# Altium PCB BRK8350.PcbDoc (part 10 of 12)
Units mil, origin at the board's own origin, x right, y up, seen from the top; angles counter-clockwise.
Board outline 9448.82 x 5905.51 mil, 8 copper layers (L1-TOP, L2-GND, L3-SIG, L4-GND, L5-PWR, L6-PWR, L7-GND, L8-BOT), stack 57.69 mil thick; 288 components, 543 nets, 1891 pads, 2032 vias.
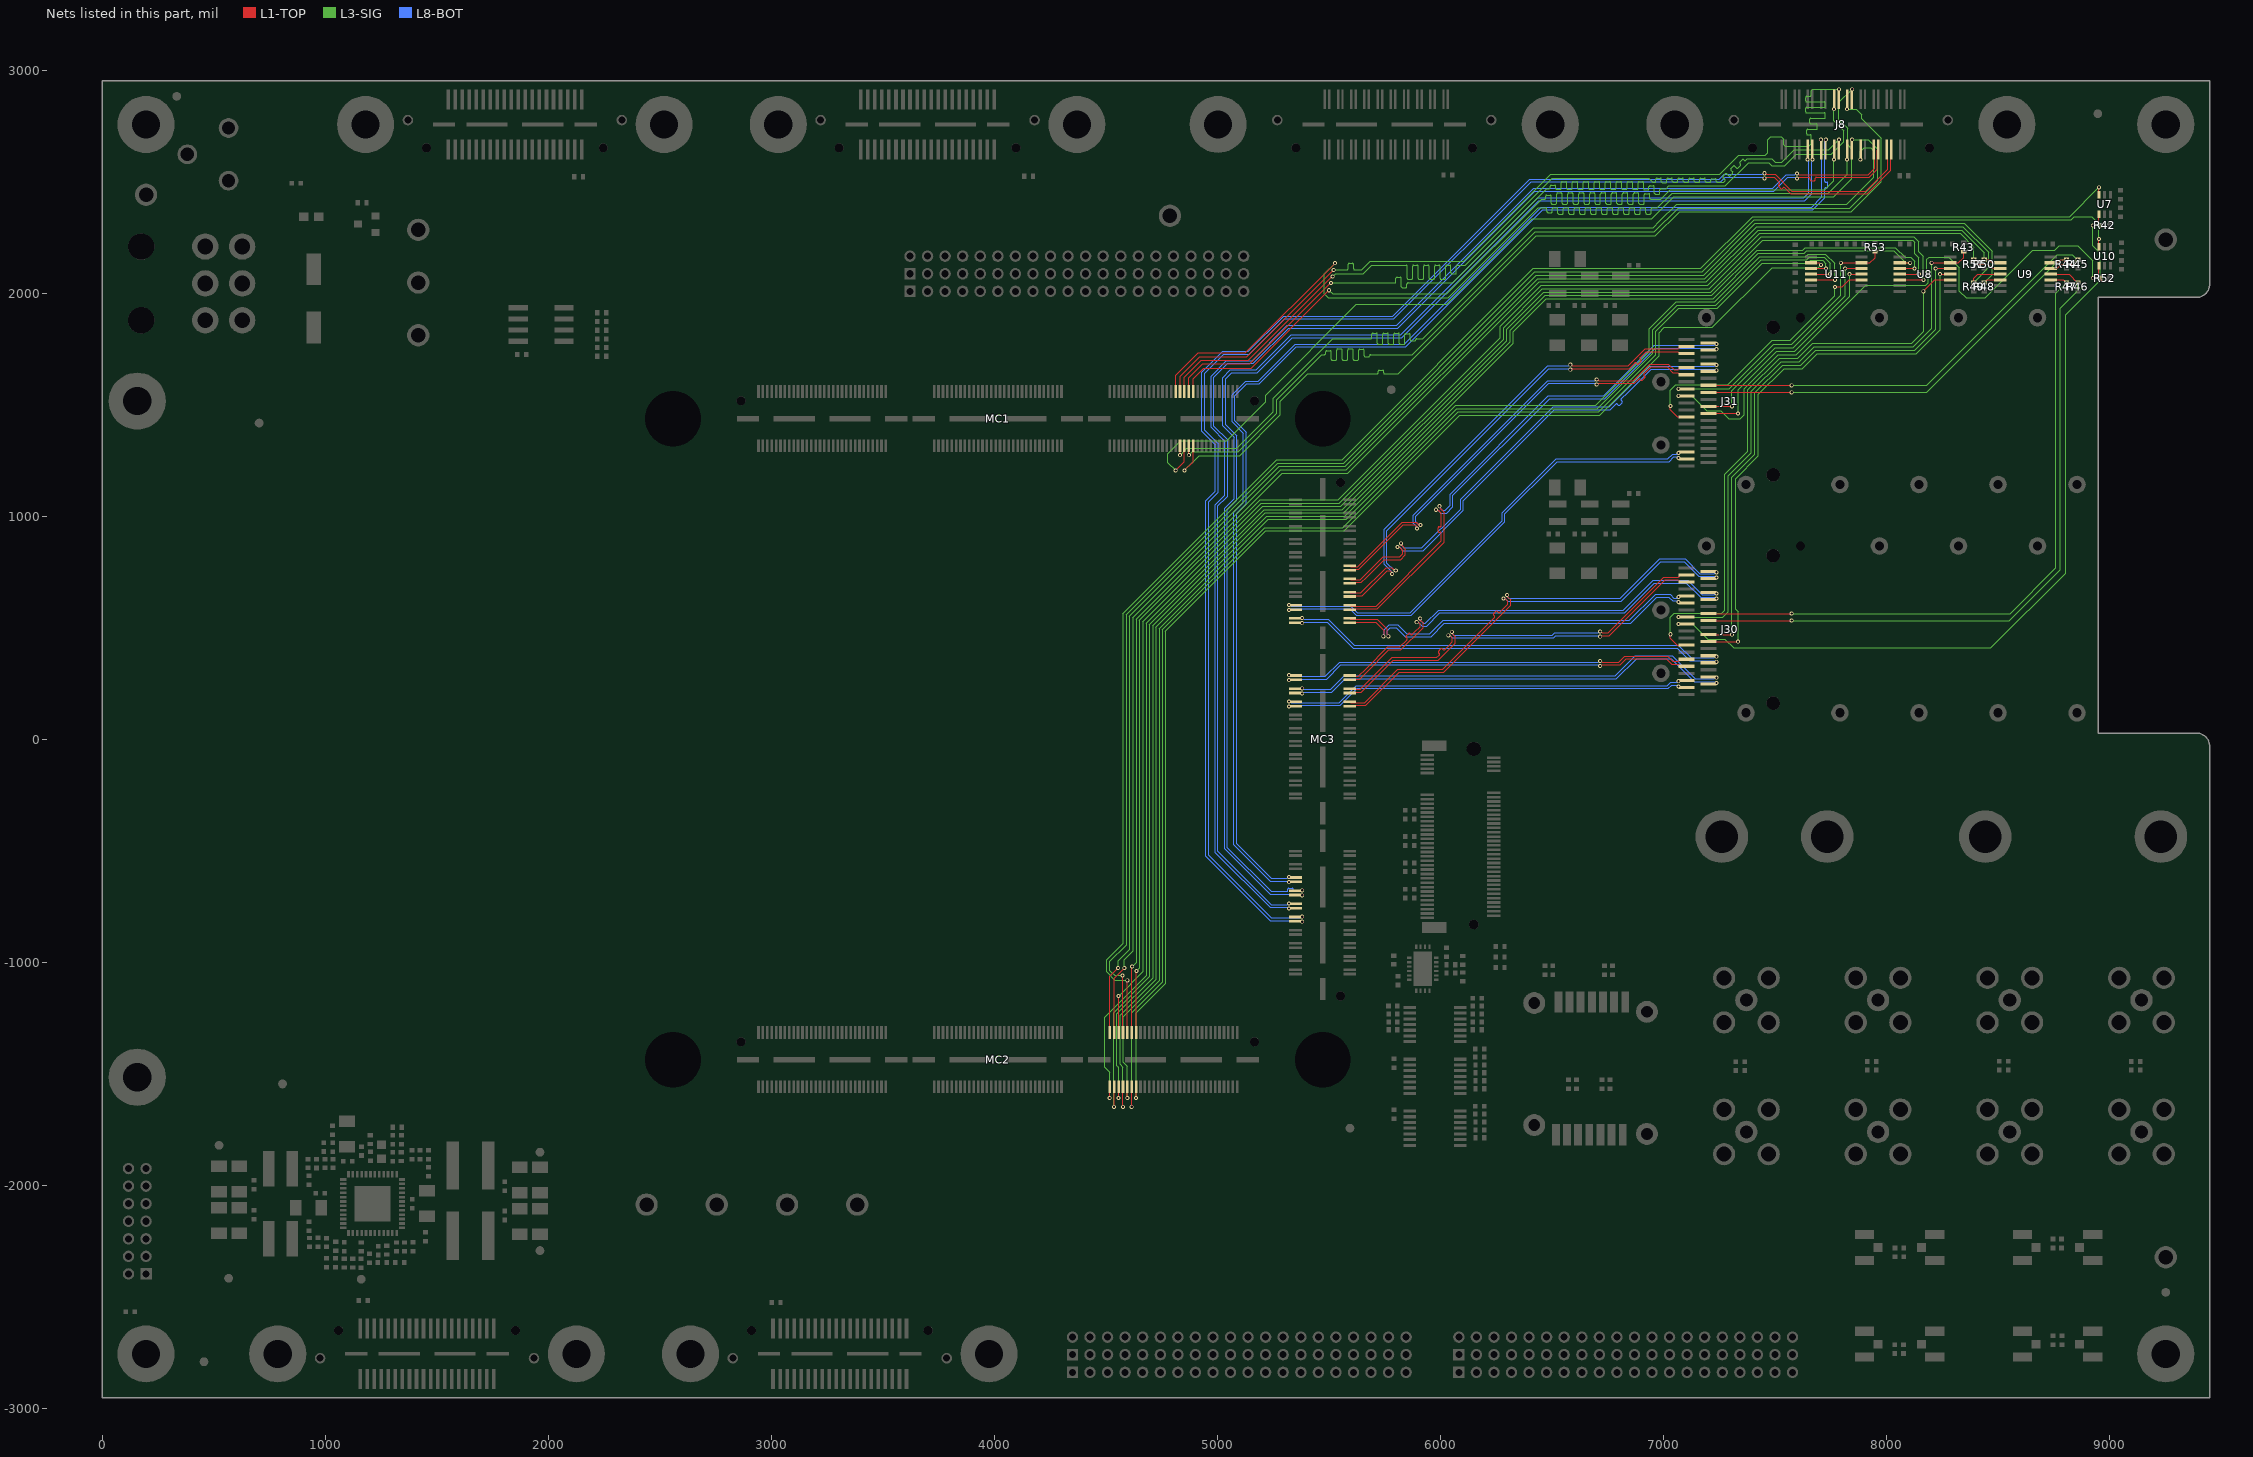
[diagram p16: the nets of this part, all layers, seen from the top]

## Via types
v1: diameter 18, hole 10, L1-TOP to L8-BOT, tented both sides, 2032 vias

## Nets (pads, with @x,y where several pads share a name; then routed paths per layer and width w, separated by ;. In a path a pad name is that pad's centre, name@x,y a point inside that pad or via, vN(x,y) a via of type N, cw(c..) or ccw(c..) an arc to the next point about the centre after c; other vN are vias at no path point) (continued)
PORTF_S1: J8.16 MC1.154 | length 4259.5
  L1-TOP w4.5: v1(4832.83,1273.38) MC1.154@4832.8,1315.41
  L3-SIG w4.6: v1(4832.83,1273.38) 4842.42,1282.97 4863.72,1304.27 5086.53,1304.27 5249.74,1467.47 5249.74,1528.52 5516.49,1795.28 5685.75,1795.28 5688.05,1795.28 ccw(c5688.05,1800.2) 5692.97,1800.2 5692.97,1815.36 cw(c5697.89,1815.36) 5697.89,1820.28 5712.65,1820.28 cw(c5712.65,1815.36) 5717.57,1815.36 5717.57,1775.2 ccw(c5722.49,1775.2) 5722.49,1770.28 5737.25,1770.28 ccw(c5737.25,1775.2) 5742.17,1775.2 5742.17,1815.36 cw(c5747.09,1815.36) 5747.09,1820.28 5761.85,1820.28 cw(c5761.85,1815.36) 5766.77,1815.36 5766.77,1775.2 ccw(c5771.69,1775.2) 5771.69,1770.28 5786.45,1770.28 ccw(c5786.45,1775.2) 5791.37,1775.2 5791.37,1815.36 cw(c5796.29,1815.36) 5796.29,1820.28 5811.05,1820.28 cw(c5811.05,1815.36) 5815.97,1815.36 5815.97,1775.2 ccw(c5820.89,1775.2) 5820.89,1770.28 5835.65,1770.28 ccw(c5835.65,1775.2) 5840.57,1775.2 5840.57,1812.92 cw(c5845.49,1812.92) 5845.49,1817.84 5860.25,1817.84 cw(c5860.25,1812.92) 5865.17,1812.92 5865.17,1790.35 ccw(c5870.09,1790.35) 5870.09,1785.43 5884.85,1785.43 ccw(c5884.85,1790.35) 5889.77,1790.35 cw(c5894.69,1790.36) 5894.69,1795.28 5906.79,1795.28 5921.55,1795.28 6418.9,2292.63 6953.82,2292.63 6984.4,2323.21 7059.09,2397.9 7822.12,2397.9 7942.94,2518.73 7942.94,2638.75 7930.12,2651.57 7899.61,2651.57 7882.61,2634.58 v1(7882.61,2598.35)
PORTF_S2: J8.17 MC1.156 | length 4259.2
  L1-TOP w4.5: v1(4813.01,1204.72) 4852.38,1244.09 MC1.156@4852.38,1315.37
  L3-SIG w4.6: v1(4813.01,1204.72) 4778.71,1239.02 4778.71,1279.38 4836.8,1337.47 5042.19,1337.47 5216.54,1511.81 5216.54,1542.27 5623.09,1948.82 6028.14,1948.82 6411.63,2332.31 6946.55,2332.31 7045.34,2431.1 7762.8,2431.1 7843.94,2512.25 7843.94,2645.23 7825.3,2663.88 7825.3,2738.68 7786.83,2777.15 7786.83,2854.48 v1(7846.05,2913.7)
PORTF_S3: J8.18 MC1.158 | length 4259.5
  L1-TOP w4.5: v1(4872.2,1273.38) MC1.158@4872.17,1315.41
  L3-SIG w4.6: v1(4872.2,1273.38) 4886.49,1287.67 5093.4,1287.67 5266.34,1460.6 5266.34,1521.64 5469.1,1724.41 5478.53,1724.41 5480.83,1724.41 ccw(c5480.83,1729.33) 5485.75,1729.33 5485.75,1736.13 cw(c5490.67,1736.13) 5490.67,1741.05 5505.43,1741.05 cw(c5505.43,1736.13) 5510.35,1736.13 5510.35,1704.33 ccw(c5515.27,1704.33) 5515.27,1699.41 5530.03,1699.41 ccw(c5530.03,1704.33) 5534.95,1704.33 5534.95,1744.49 cw(c5539.87,1744.49) 5539.87,1749.41 5554.63,1749.41 cw(c5554.63,1744.49) 5559.55,1744.49 5559.55,1704.33 ccw(c5564.47,1704.33) 5564.47,1699.41 5579.23,1699.41 ccw(c5579.23,1704.33) 5584.15,1704.33 5584.15,1744.49 cw(c5589.07,1744.49) 5589.07,1749.41 5603.83,1749.41 cw(c5603.83,1744.49) 5608.75,1744.49 5608.75,1704.33 ccw(c5613.67,1704.33) 5613.67,1699.41 5628.43,1699.41 ccw(c5628.43,1704.33) 5633.35,1704.33 5633.35,1742.78 cw(c5638.27,1742.78) 5638.27,1747.7 5653.03,1747.7 cw(c5653.03,1742.78) 5657.95,1742.78 5657.95,1719.49 ccw(c5662.87,1719.49) 5662.87,1714.57 5677.63,1714.57 ccw(c5677.63,1719.49) 5682.55,1719.49 cw(c5687.47,1719.49) 5687.47,1724.41 5763.78,1724.41 5874.16,1724.41 6424.35,2274.6 6959.26,2274.6 7065.97,2381.3 7835.04,2381.3 7960.66,2506.92 7960.66,2645.64 7918.58,2687.72 v1(7846.05,2687.72)
PORTF_S4: J8.19 MC1.160 | length 4259.5
  L1-TOP w4.5: v1(4852.38,1204.72) 4891.75,1244.09 MC1.160@4891.75,1315.37
  L3-SIG w4.6: v1(4852.38,1204.72) 4918.72,1271.07 5100.28,1271.07 5282.94,1453.72 5282.94,1514.77 5405.97,1637.8 5713.63,1637.8 5715.93,1637.8 ccw(c5715.93,1642.72) 5720.85,1642.72 5720.85,1648.69 cw(c5725.77,1648.69) 5725.77,1653.61 5740.53,1653.61 cw(c5740.53,1648.69) 5745.45,1648.69 5745.45,1642.72 ccw(c5750.37,1642.72) 5750.37,1637.8 5787.4,1637.8 5811.02,1637.8 6429.19,2255.96 6964.1,2255.96 7072.85,2364.7 7842.13,2364.7 7977.27,2499.84 7977.27,2693.99 7889.77,2781.49 7889.77,2799.17 7864.61,2824.33 v1(7823.55,2824.33)
PORTF_S5: J8.20 MC1.151 | length 4259.5
  L1-TOP w4.5: MC1.151@4813.01,1558.68 4813.01,1630.76 4913.78,1731.53 5125.52,1731.53 5527.56,2133.57 v1(5527.56,2133.86)
  L3-SIG w4.6: v1(5527.56,2133.86) 5480.32,2086.61 5480.32,1996.06 5497.05,1979.33 6035.18,1979.33 6437.74,2381.89 6449.11,2381.89 6472.76,2381.89 cw(c6472.76,2376.97) 6477.68,2376.97 6477.68,2365.73 ccw(c6482.6,2365.73) 6482.6,2360.81 6497.36,2360.81 ccw(c6497.36,2365.73) 6502.28,2365.73 6502.28,2376.97 cw(c6507.2,2376.97) 6507.2,2381.89 6521.96,2381.89 cw(c6521.96,2376.97) 6526.88,2376.97 6526.88,2358.78 ccw(c6531.8,2358.78) 6531.8,2353.86 6546.56,2353.86 ccw(c6546.56,2358.78) 6551.48,2358.78 6551.48,2376.97 cw(c6556.4,2376.97) 6556.4,2381.89 6571.16,2381.89 cw(c6571.16,2376.97) 6576.08,2376.97 6576.08,2358.78 ccw(c6581,2358.78) 6581,2353.86 6595.76,2353.86 ccw(c6595.76,2358.78) 6600.68,2358.78 6600.68,2376.97 cw(c6605.6,2376.97) 6605.6,2381.89 6620.36,2381.89 cw(c6620.36,2376.97) 6625.28,2376.97 6625.28,2358.78 ccw(c6630.2,2358.78) 6630.2,2353.86 6644.96,2353.86 ccw(c6644.96,2358.78) 6649.88,2358.78 6649.88,2376.97 cw(c6654.8,2376.97) 6654.8,2381.89 6669.56,2381.89 cw(c6669.56,2376.97) 6674.48,2376.97 6674.48,2358.78 ccw(c6679.4,2358.78) 6679.4,2353.86 6694.16,2353.86 ccw(c6694.16,2358.78) 6699.08,2358.78 6699.08,2376.97 cw(c6704,2376.97) 6704,2381.89 6718.76,2381.89 cw(c6718.76,2376.97) 6723.68,2376.97 6723.68,2358.78 ccw(c6728.6,2358.78) 6728.6,2353.86 6743.36,2353.86 ccw(c6743.36,2358.78) 6748.28,2358.78 6748.28,2376.97 cw(c6753.2,2376.97) 6753.2,2381.89 6767.96,2381.89 cw(c6767.96,2376.97) 6772.88,2376.97 6772.88,2358.78 ccw(c6777.8,2358.78) 6777.8,2353.86 6792.56,2353.86 ccw(c6792.56,2358.78) 6797.48,2358.78 6797.48,2376.97 cw(c6802.4,2376.97) 6802.4,2381.89 6817.16,2381.89 cw(c6817.16,2376.97) 6822.08,2376.97 6822.08,2358.78 ccw(c6827,2358.78) 6827,2353.86 6841.76,2353.86 ccw(c6841.76,2358.78) 6846.68,2358.78 6846.68,2376.97 cw(c6851.6,2376.97) 6851.6,2381.89 6866.36,2381.89 cw(c6866.36,2376.97) 6871.28,2376.97 6871.28,2358.78 ccw(c6876.2,2358.78) 6876.2,2353.86 6890.96,2353.86 ccw(c6890.96,2358.78) 6895.88,2358.78 6895.88,2376.97 cw(c6900.8,2376.97) 6900.8,2381.89 6915.56,2381.89 cw(c6915.56,2376.97) 6920.48,2376.97 6920.48,2359.23 ccw(c6925.4,2359.23) 6925.4,2354.31 6940.16,2354.31 ccw(c6940.16,2359.23) 6945.08,2359.23 6945.08,2376.97 cw(c6950,2376.97) 6950,2381.89 6952.3,2381.89 6972.65,2381.89 7038.47,2447.7 7739.6,2447.7 7823.55,2531.66 v1(7823.55,2598.35)
PORTF_S6: J8.21 MC1.153 | length 4259.2
  L1-TOP w4.5: MC1.153@4832.69,1558.68 4832.69,1627.11 4920.61,1715.03 5132.35,1715.03 5521.29,2103.96 v1(5521.47,2103.96)
  L3-SIG w4.6: v1(5521.47,2103.96) 5578.74,2103.96 5581.04,2103.96 ccw(c5581.04,2108.88) 5585.96,2108.88 5585.96,2128.44 cw(c5590.88,2128.44) 5590.88,2133.36 5605.64,2133.36 cw(c5605.64,2128.44) 5610.56,2128.44 5610.56,2108.88 ccw(c5615.48,2108.88) 5615.48,2103.96 5636.36,2103.96 5647.27,2103.96 5685.34,2142.04 6103.98,2142.04 6494.33,2532.39 7252.86,2532.39 7338.32,2617.85 7456.39,2617.85 7467.52,2628.97 7467.52,2687.25 7480.24,2699.97 7528.37,2699.97 7539.37,2688.98 7539.37,2665.14 7546.87,2657.65 7651.41,2657.65 7662.4,2668.64 7662.4,2702.27 7662.4,2704.57 ccw(c7657.48,2704.57) 7657.48,2709.49 7646.65,2709.49 cw(c7646.65,2714.41) 7641.73,2714.41 7641.73,2729.17 cw(c7646.65,2729.17) 7646.65,2734.09 7685.68,2734.09 ccw(c7685.68,2739.01) 7690.6,2739.01 7690.6,2753.77 ccw(c7685.68,2753.77) 7685.68,2758.69 7661.12,2758.69 cw(c7661.12,2763.61) 7656.2,2763.61 7656.2,2778.37 cw(c7661.12,2778.37) 7661.12,2783.29 7721.06,2783.29 ccw(c7721.06,2788.21) 7725.98,2788.21 7725.98,2802.97 ccw(c7721.06,2802.97) 7721.06,2807.89 7642.32,2807.89 cw(c7642.32,2812.81) 7637.4,2812.81 7637.4,2827.57 cw(c7642.32,2827.57) 7642.32,2832.49 7721.06,2832.49 ccw(c7721.06,2837.41) 7725.98,2837.41 7725.98,2852.17 ccw(c7721.06,2852.17) 7721.06,2857.09 7642.32,2857.09 cw(c7642.32,2862.01) 7637.4,2862.01 7637.4,2876.77 cw(c7642.32,2876.77) 7642.32,2881.69 7657.48,2881.69 ccw(c7657.48,2886.61) 7662.4,2886.61 7662.4,2901.57 7662.4,2906.5 7669.61,2913.7 7746.83,2913.7 7746.87,2913.66 7757.06,2913.66 7757.11,2913.7 v1(7787,2913.7)
PORTF_S7: J8.22 MC1.155 | length 4259.2
  L1-TOP w4.5: MC1.155@4852.38,1558.68 4852.38,1623.46 4927.45,1698.53 5139.18,1698.53 5515.41,2074.75 v1(5517.21,2074.75)
  L3-SIG w4.6: v1(5517.21,2074.75) 5529.82,2087.36 5654.29,2087.36 5692.36,2125.44 5818.9,2125.44 5845.8,2125.44 cw(c5845.8,2120.52) 5850.72,2120.52 5850.72,2067.06 ccw(c5855.64,2067.06) 5855.64,2062.14 5870.4,2062.14 ccw(c5870.4,2067.06) 5875.32,2067.06 5875.32,2120.52 cw(c5880.24,2120.52) 5880.24,2125.44 5895,2125.44 cw(c5895,2120.52) 5899.92,2120.52 5899.92,2067.06 ccw(c5904.84,2067.06) 5904.84,2062.14 5919.6,2062.14 ccw(c5919.6,2067.06) 5924.52,2067.06 5924.52,2120.52 cw(c5929.44,2120.52) 5929.44,2125.44 5944.2,2125.44 cw(c5944.2,2120.52) 5949.12,2120.52 5949.12,2067.06 ccw(c5954.04,2067.06) 5954.04,2062.14 5968.8,2062.14 ccw(c5968.8,2067.06) 5973.72,2067.06 5973.72,2120.52 cw(c5978.64,2120.52) 5978.64,2125.44 5993.4,2125.44 cw(c5993.4,2120.52) 5998.32,2120.52 5998.32,2067.06 ccw(c6003.24,2067.06) 6003.24,2062.14 6018,2062.14 ccw(c6018,2067.06) 6022.92,2067.06 6022.92,2120.52 cw(c6027.84,2120.52) 6027.84,2125.44 6042.6,2125.44 cw(c6042.6,2120.52) 6047.52,2120.52 6047.52,2091.62 ccw(c6052.44,2091.62) 6052.44,2086.7 6067.2,2086.7 ccw(c6067.2,2091.62) 6072.12,2091.62 6072.12,2120.52 cw(c6077.04,2120.52) 6077.04,2125.44 6086.9,2125.44 6110.86,2125.44 6501.21,2515.79 6934.14,2515.79 6952.42,2497.5 6959.34,2497.5 6961.64,2497.5 ccw(c6961.64,2502.42) 6966.56,2502.42 6966.56,2510.87 cw(c6971.48,2510.87) 6971.48,2515.79 6986.24,2515.79 cw(c6986.24,2510.87) 6991.16,2510.87 6991.16,2500.02 ccw(c6996.08,2500.02) 6996.08,2495.1 7010.84,2495.1 ccw(c7010.84,2500.02) 7015.76,2500.02 7015.76,2510.87 cw(c7020.68,2510.87) 7020.68,2515.79 7035.44,2515.79 cw(c7035.44,2510.87) 7040.36,2510.87 7040.36,2502.42 ccw(c7045.28,2502.42) 7045.28,2497.5 7060.04,2497.5 ccw(c7060.04,2502.42) 7064.96,2502.42 7064.96,2510.87 cw(c7069.88,2510.87) 7069.88,2515.79 7084.64,2515.79 cw(c7084.64,2510.87) 7089.56,2510.87 7089.56,2502.42 ccw(c7094.48,2502.42) 7094.48,2497.5 7109.24,2497.5 ccw(c7109.24,2502.42) 7114.16,2502.42 7114.16,2510.87 cw(c7119.08,2510.87) 7119.08,2515.79 7133.84,2515.79 cw(c7133.84,2510.87) 7138.76,2510.87 7138.76,2502.42 ccw(c7143.68,2502.42) 7143.68,2497.5 7158.44,2497.5 ccw(c7158.44,2502.42) 7163.36,2502.42 7163.36,2510.87 cw(c7168.28,2510.87) 7168.28,2515.79 7183.04,2515.79 cw(c7183.04,2510.87) 7187.96,2510.87 7187.96,2502.42 ccw(c7192.88,2502.42) 7192.88,2497.5 7207.64,2497.5 ccw(c7207.64,2502.42) 7212.56,2502.42 7212.56,2506.8 cw(c7217.48,2506.8) 7217.48,2511.72 7232.24,2511.72 cw(c7232.24,2506.8) 7237.16,2506.8 7237.16,2502.42 ccw(c7242.08,2502.42) 7242.08,2497.5 7252.86,2497.5 7270.98,2497.5 7273.55,2500.08 7275.18,2501.7 ccw(c7271.7,2505.18) 7275.18,2508.66 7267.37,2516.47 cw(c7270.85,2519.95) 7267.37,2523.43 7277.81,2533.86 cw(c7281.29,2530.38) 7284.77,2533.86 7292.58,2526.06 ccw(c7296.05,2529.54) 7299.53,2526.06 7309.97,2536.49 ccw(c7306.49,2539.97) 7309.97,2543.45 7302.16,2551.26 cw(c7305.64,2554.74) 7302.16,2558.22 7312.6,2568.65 cw(c7316.08,2565.17) 7319.56,2568.65 7327.36,2560.85 ccw(c7330.84,2564.33) 7334.32,2560.85 7344.76,2571.28 ccw(c7341.28,2574.76) 7344.76,2578.24 7342.63,2580.37 cw(c7346.11,2583.85) 7342.63,2587.33 7353.07,2597.77 cw(c7356.55,2594.29) 7360.02,2597.77 7362.15,2595.64 ccw(c7365.63,2599.12) 7369.11,2595.64 7374.72,2601.25 7378.16,2601.25 7485.37,2601.25 7500.98,2585.63 7530.51,2585.63 7586.61,2641.73 7741.01,2641.73 v1(7787,2687.72)
PORTF_S8: J8.23 MC1.157 | length 4259.2
  L1-TOP w4.5: MC1.157@4872.06,1558.68 4872.06,1619.81 4934.28,1682.03 5146.02,1682.03 5509.53,2045.54 v1(5509.96,2045.54)
  L3-SIG w4.6: v1(5509.96,2045.54) 5793.47,2045.54 5795.77,2045.54 ccw(c5795.77,2050.46) 5800.69,2050.46 5800.69,2065.62 cw(c5805.61,2065.62) 5805.61,2070.54 5820.37,2070.54 cw(c5820.37,2065.62) 5825.29,2065.62 5825.29,2029.25 ccw(c5830.21,2029.25) 5830.21,2024.33 5844.97,2024.33 ccw(c5844.97,2029.25) 5849.89,2029.25 5849.89,2040.62 cw(c5854.81,2040.62) 5854.81,2045.54 5875.62,2045.54 6054.43,2045.54 6477.4,2468.5 6485.23,2468.5 6487.53,2468.5 ccw(c6487.53,2473.42) 6492.45,2473.42 6492.45,2478.63 cw(c6497.37,2478.63) 6497.37,2483.55 6512.13,2483.55 cw(c6512.13,2478.63) 6517.05,2478.63 6517.05,2470.4 ccw(c6521.97,2470.4) 6521.97,2465.48 6536.73,2465.48 ccw(c6536.73,2470.4) 6541.65,2470.4 6541.65,2494.27 cw(c6546.57,2494.27) 6546.57,2499.19 6561.33,2499.19 cw(c6561.33,2494.27) 6566.25,2494.27 6566.25,2470.4 ccw(c6571.17,2470.4) 6571.17,2465.48 6585.93,2465.48 ccw(c6585.93,2470.4) 6590.85,2470.4 6590.85,2494.27 cw(c6595.77,2494.27) 6595.77,2499.19 6610.53,2499.19 cw(c6610.53,2494.27) 6615.45,2494.27 6615.45,2470.4 ccw(c6620.37,2470.4) 6620.37,2465.48 6635.13,2465.48 ccw(c6635.13,2470.4) 6640.05,2470.4 6640.05,2494.27 cw(c6644.97,2494.27) 6644.97,2499.19 6659.73,2499.19 cw(c6659.73,2494.27) 6664.65,2494.27 6664.65,2470.4 ccw(c6669.57,2470.4) 6669.57,2465.48 6684.33,2465.48 ccw(c6684.33,2470.4) 6689.25,2470.4 6689.25,2494.27 cw(c6694.17,2494.27) 6694.17,2499.19 6708.93,2499.19 cw(c6708.93,2494.27) 6713.85,2494.27 6713.85,2470.4 ccw(c6718.77,2470.4) 6718.77,2465.48 6733.53,2465.48 ccw(c6733.53,2470.4) 6738.45,2470.4 6738.45,2494.27 cw(c6743.37,2494.27) 6743.37,2499.19 6758.13,2499.19 cw(c6758.13,2494.27) 6763.05,2494.27 6763.05,2470.4 ccw(c6767.97,2470.4) 6767.97,2465.48 6782.73,2465.48 ccw(c6782.73,2470.4) 6787.65,2470.4 6787.65,2494.27 cw(c6792.57,2494.27) 6792.57,2499.19 6807.33,2499.19 cw(c6807.33,2494.27) 6812.25,2494.27 6812.25,2470.4 ccw(c6817.17,2470.4) 6817.17,2465.48 6831.93,2465.48 ccw(c6831.93,2470.4) 6836.85,2470.4 6836.85,2494.27 cw(c6841.77,2494.27) 6841.77,2499.19 6856.53,2499.19 cw(c6856.53,2494.27) 6861.45,2494.27 6861.45,2470.4 ccw(c6866.37,2470.4) 6866.37,2465.48 6881.13,2465.48 ccw(c6881.13,2470.4) 6886.05,2470.4 6886.05,2494.27 cw(c6890.97,2494.27) 6890.97,2499.19 6905.73,2499.19 cw(c6905.73,2494.27) 6910.65,2494.27 6910.65,2467.68 ccw(c6915.57,2467.68) 6915.57,2462.76 6930.33,2462.76 ccw(c6930.33,2467.68) 6935.25,2467.68 6935.25,2475.98 cw(c6940.17,2475.98) 6940.17,2480.9 6954.93,2480.9 cw(c6954.93,2475.98) 6959.85,2475.98 6959.85,2448.42 ccw(c6964.77,2448.42) 6964.77,2443.5 6979.53,2443.5 ccw(c6979.53,2448.42) 6984.45,2448.42 6984.45,2463.58 cw(c6989.37,2463.58) 6989.37,2468.5 7003.1,2468.5 7011.96,2468.5 7024.36,2480.9 7277.85,2480.9 7381.6,2584.65 7472.17,2584.65 7485.95,2570.87 7543.31,2570.87 7594.49,2622.05 7752.95,2622.05 7809.06,2678.15 7809.06,2727.43 7764.5,2771.98 v1(7764.5,2824.33)
PORTF_S9: J8.24 MC1.159 | length 4259.2
  L1-TOP w4.5: MC1.159@4891.75,1558.68 4891.75,1616.16 4939.62,1664.03 5151.36,1664.03 v1(5500,2012.67)
  L3-SIG w4.6: v1(5500,2012.67) 5516.61,1996.06 6028.44,1996.06 6453.63,2421.26 6464.57,2421.26 6466.87,2421.26 ccw(c6466.87,2426.18) 6471.79,2426.18 6471.79,2434.49 cw(c6476.71,2434.49) 6476.71,2439.41 6491.47,2439.41 cw(c6491.47,2434.49) 6496.39,2434.49 6496.39,2403.41 ccw(c6501.31,2403.41) 6501.31,2398.49 6516.07,2398.49 ccw(c6516.07,2403.41) 6520.99,2403.41 6520.99,2443.96 cw(c6525.91,2443.96) 6525.91,2448.88 6540.67,2448.88 cw(c6540.67,2443.96) 6545.59,2443.96 6545.59,2403.41 ccw(c6550.51,2403.41) 6550.51,2398.49 6565.27,2398.49 ccw(c6565.27,2403.41) 6570.19,2403.41 6570.19,2443.96 cw(c6575.11,2443.96) 6575.11,2448.88 6589.87,2448.88 cw(c6589.87,2443.96) 6594.79,2443.96 6594.79,2403.41 ccw(c6599.71,2403.41) 6599.71,2398.49 6614.47,2398.49 ccw(c6614.47,2403.41) 6619.39,2403.41 6619.39,2443.96 cw(c6624.31,2443.96) 6624.31,2448.88 6639.07,2448.88 cw(c6639.07,2443.96) 6643.99,2443.96 6643.99,2403.41 ccw(c6648.91,2403.41) 6648.91,2398.49 6663.67,2398.49 ccw(c6663.67,2403.41) 6668.59,2403.41 6668.59,2443.96 cw(c6673.51,2443.96) 6673.51,2448.88 6688.27,2448.88 cw(c6688.27,2443.96) 6693.19,2443.96 6693.19,2403.41 ccw(c6698.11,2403.41) 6698.11,2398.49 6712.87,2398.49 ccw(c6712.87,2403.41) 6717.79,2403.41 6717.79,2443.96 cw(c6722.71,2443.96) 6722.71,2448.88 6737.47,2448.88 cw(c6737.47,2443.96) 6742.39,2443.96 6742.39,2403.41 ccw(c6747.31,2403.41) 6747.31,2398.49 6762.07,2398.49 ccw(c6762.07,2403.41) 6766.99,2403.41 6766.99,2443.96 cw(c6771.91,2443.96) 6771.91,2448.88 6786.67,2448.88 cw(c6786.67,2443.96) 6791.59,2443.96 6791.59,2403.41 ccw(c6796.51,2403.41) 6796.51,2398.49 6811.27,2398.49 ccw(c6811.27,2403.41) 6816.19,2403.41 6816.19,2443.96 cw(c6821.11,2443.96) 6821.11,2448.88 6835.87,2448.88 cw(c6835.87,2443.96) 6840.79,2443.96 6840.79,2403.41 ccw(c6845.71,2403.41) 6845.71,2398.49 6860.47,2398.49 ccw(c6860.47,2403.41) 6865.39,2403.41 6865.39,2443.96 cw(c6870.31,2443.96) 6870.31,2448.88 6885.07,2448.88 cw(c6885.07,2443.96) 6889.99,2443.96 6889.99,2403.41 ccw(c6894.91,2403.41) 6894.91,2398.49 6909.67,2398.49 ccw(c6909.67,2403.41) 6914.59,2403.41 6914.59,2441.24 cw(c6919.51,2441.24) 6919.51,2446.16 6934.27,2446.16 cw(c6934.27,2441.24) 6939.19,2441.24 6939.19,2426.18 ccw(c6944.11,2426.18) 6944.11,2421.26 6985.73,2421.26 6988.19,2421.26 7031.23,2464.3 7031.59,2464.3 7724.14,2464.3 7764.5,2504.65 v1(7764.5,2598.35)
PORTF_TX0N: J8.8 MC3.104 | length 6375.1
  L1-TOP w4.2: v1(7452.76,2537.24) 7456.49,2537.24 7461.44,2532.29 7501.28,2532.29 7576.09,2457.48 7907.86,2457.48 8005.67,2555.29 8005.67,2597.99 8005.54,2598.12 8005.54,2639.62 J8.8@8002.13,2643.03
  L8-BOT w4.2: v1(5380.17,-818.41) 5376.44,-818.41 5371.4,-813.37 5236.14,-813.37 4948.47,-525.71 4948.47,1069.01 4952.17,1072.7 4991.33,1111.87 4991.33,1256.42 4991.33,1319.33 4929.85,1380.8 4929.85,1645.1 5023.59,1738.85 5138.72,1738.85 5296.59,1896.72 5786.6,1896.72 6401.03,2511.14 7251.3,2511.14 7272.44,2532.29 7444.07,2532.29 7449.02,2537.24 v1(7452.76,2537.24)
PORTF_TX0P: J8.6 MC3.102 | length 6375.1
  L1-TOP w4.2: v1(7452.76,2514.74) 7456.49,2514.74 7461.44,2519.69 7496.06,2519.69 7501.28,2514.47 7519.88,2495.87 cw(c7516.46,2492.45) 7519.88,2489.02 7516.41,2485.55 ccw(c7519.83,2482.13) 7516.41,2478.71 7526.67,2468.44 ccw(c7530.1,2471.86) 7533.52,2468.44 7536.99,2471.91 cw(c7540.41,2468.49) 7543.84,2471.91 7561.68,2454.07 7570.87,2444.88 7913.08,2444.88 8018.27,2550.07 8018.27,2597.99 8018.4,2598.12 8018.4,2639.62 J8.6@8021.81,2643.03
  L8-BOT w4.2: v1(5380.17,-795.73) 5376.44,-795.73 5371.4,-800.77 5241.36,-800.77 4961.07,-520.49 4961.07,1063.79 5000.24,1102.96 5003.93,1106.65 5003.93,1262.72 5003.93,1324.54 4942.45,1386.02 4942.45,1639.88 5028.81,1726.25 5143.94,1726.25 5152.85,1735.15 5301.81,1884.12 5791.82,1884.12 6406.25,2498.54 7227.85,2498.54 7256.52,2498.54 7277.66,2519.69 7444.07,2519.69 7449.02,2514.74 v1(7452.76,2514.74)
PORTF_TX1N: J8.12 MC3.100 | length 6064.1
  L1-TOP w4.2: v1(7598.43,2536.45) 7601.35,2536.45 7606.3,2531.5 7917.64,2531.5 7946.55,2560.41 7946.55,2585.32 7946.48,2585.39 7946.48,2598.12 ; J8.12@7943.07,2643.03 7946.48,2639.62 7946.48,2598.12 ; 7946.61,2597.99 7946.48,2598.12
  L8-BOT w4.2: v1(5321.43,-759.36) 5317.7,-759.36 5312.66,-754.32 5236.2,-754.32 4990.27,-508.39 4990.27,1051.7 4993.97,1055.39 5033.13,1094.55 5033.13,1336.64 4971.65,1398.12 4971.65,1627.79 5040.91,1697.05 5156.04,1697.05 5313.91,1854.92 5803.91,1854.92 6418.34,2469.34 7314.51,2469.34 7331.83,2469.34 7489.03,2469.34 7551.18,2531.5 7589.74,2531.5 7594.69,2536.45 v1(7598.43,2536.45)
PORTF_TX1P: J8.10 MC3.98 | length 6063.9
  L1-TOP w4.2: v1(7598.43,2513.95) 7601.35,2513.95 7606.3,2518.9 7625.98,2518.9 7652.28,2518.9 cw(c7652.28,2514.06) 7657.12,2514.06 7657.12,2509.15 ccw(c7661.96,2509.15) 7661.96,2504.31 7676.48,2504.31 ccw(c7676.48,2509.15) 7681.32,2509.15 7681.32,2514.06 cw(c7686.16,2514.06) 7686.16,2518.9 7716.54,2518.9 7922.86,2518.9 7959.15,2555.19 7959.15,2585.25 7959.21,2585.32 7959.21,2597.99 7959.34,2598.12 7959.34,2639.62 J8.10@7962.76,2643.03
  L8-BOT w4.2: v1(5321.43,-736.67) 5317.7,-736.67 5312.66,-741.72 5241.42,-741.72 5002.87,-503.17 5002.87,1046.48 5042.04,1085.64 5045.73,1089.33 5045.73,1341.86 4984.25,1403.34 4984.25,1622.57 5046.13,1684.45 5161.26,1684.45 5170.17,1693.35 5319.13,1842.32 5809.13,1842.32 6423.56,2456.74 7309.3,2456.74 7339.21,2456.74 7494.25,2456.74 7556.4,2518.9 7589.74,2518.9 7594.69,2513.95 v1(7598.43,2513.95)
PORTF_TX2N: J8.32 MC3.96 | length 5706.2
  L8-BOT w4.2: v1(5380.17,-700.3) 5376.44,-700.3 5371.4,-695.26 5236.26,-695.26 5032.07,-491.08 5032.07,1034.38 5035.77,1038.07 5074.93,1077.24 5074.93,1354.14 5024.34,1404.73 5024.34,1621.36 5058.22,1655.25 5173.35,1655.25 5331.22,1813.12 5821.22,1813.12 6435.65,2427.54 7628.33,2427.54 7651.34,2450.55 7651.34,2578.74 7651.34,2589.66 7646.39,2594.61 v1(7646.39,2598.35)
PORTF_TX2P: J8.30 MC3.94 | length 5706.2
  L8-BOT w4.2: v1(5380.17,-677.62) 5376.44,-677.62 5371.48,-682.58 5371.4,-682.66 5345.17,-682.66 cw(c5345.17,-677.82) 5340.33,-677.82 5340.33,-672.91 ccw(c5335.49,-672.91) 5335.49,-668.07 5320.97,-668.07 ccw(c5320.97,-672.91) 5316.13,-672.91 5316.13,-677.82 cw(c5311.29,-677.82) 5311.29,-682.66 5297.67,-682.66 5241.48,-682.66 5044.67,-485.86 5044.67,1029.16 5087.53,1072.02 5087.53,1250.12 5087.53,1359.36 5036.94,1409.95 5036.94,1616.14 5063.44,1642.65 5178.57,1642.65 5187.48,1651.55 5336.44,1800.52 5826.44,1800.52 6440.87,2414.94 7620.95,2414.94 7633.55,2414.94 7663.94,2445.33 7663.94,2578.74 7663.94,2589.66 7668.89,2594.61 v1(7668.89,2598.35)
PORTF_TX3N: J8.28 MC3.92 | length 5643.9
  L8-BOT w4.2: v1(5321.43,-641.25) 5317.7,-641.25 5312.66,-636.21 5236.32,-636.21 5073.87,-473.76 5073.87,1017.07 5116.73,1059.92 5116.73,1262.21 5116.73,1371.46 5066.14,1422.05 5066.14,1544.65 5126.92,1605.43 5182.65,1605.43 5348.53,1771.32 5838.54,1771.32 6452.97,2385.74 7349.14,2385.74 7664.6,2385.74 7710.39,2431.54 7710.39,2578.74 7710.39,2679.03 7705.44,2683.98 v1(7705.44,2687.72)
PORTF_TX3P: J8.26 MC3.90 | length 5643.9
  L8-BOT w4.2: v1(5321.43,-618.56) 5317.7,-618.56 5312.66,-623.61 5241.53,-623.61 5086.47,-468.55 5086.47,1011.85 5129.33,1054.71 5129.33,1065.14 5129.33,1267.43 5129.33,1376.68 5078.74,1427.27 5078.74,1539.43 5132.14,1592.83 5187.86,1592.83 5196.77,1601.74 5353.75,1758.72 5843.76,1758.72 6458.19,2373.15 7343.92,2373.15 ; 7343.92,2373.15 7669.82,2373.15 7722.99,2426.32 7722.99,2441.51 7722.99,2467.81 cw(c7727.83,2467.81) 7727.83,2472.65 7732.74,2472.65 ccw(c7732.74,2477.49) 7737.58,2477.49 7737.58,2492.01 ccw(c7732.74,2492.01) 7732.74,2496.85 7727.83,2496.85 cw(c7727.83,2501.69) 7722.99,2501.69 7722.99,2543.31 7722.99,2578.74 7722.99,2679.03 7727.94,2683.98 v1(7727.94,2687.72)
QSFP_1_INT_B: MC2.129 U7.3 | length 7182.3
  L1-TOP w5: v1(4596.15,-1081.12) 4596.31,-1081.29 4596.31,-1315.17 MC2.129@4596.47,-1315.34 ; U7.3@8952.76,2440.94 v1(8952.76,2474.41)
  L3-SIG w5: v1(4596.15,-1081.12) 4540.33,-1081.12 4503.02,-1043.81 4503.02,-989.58 4575.67,-916.93 4575.67,563.38 5265.2,1252.91 5560,1252.91 6417.29,2110.2 7167.59,2110.2 7400.21,2342.82 8821.17,2342.82 v1(8952.76,2474.41)
QSFP_1_INT_B_3V3: J30.28 R42.1 U7.4 | length 3634.2
  L1-TOP w5: v1(8925.2,2303.15) R42.1@8958.66,2303.15 ; R42.1@8952.76,2309.06 U7.4@8952.76,2354.33
  L3-SIG w5: v1(7067.69,515.75) 7131.39,515.75 7198.31,448.82 7275.59,448.82 7314.96,409.45 8468.5,409.45 8803.15,744.09 8803.15,1902.58 8958.66,2058.1 8958.66,2179.13 8925.2,2212.6 v1(8925.2,2303.15)
QSFP_1_LP_MODE: MC2.125 U8.5 | length 6407.8
  L1-TOP w4.5: U8.5@8059.06,2059.05 8059.32,2059.32 v1(8166.39,2059.32)
  L1-TOP w5: MC2.125@4557.1,-1315.34 v1(4557.09,-1151.91)
  L3-SIG w5: v1(4557.09,-1151.91) 4665.67,-1043.33 4665.67,526.1 5197.47,1057.9 5547.62,1057.9 6283.02,1793.3 6283.02,1844.89 6457.27,2019.15 7205.31,2019.15 7438.78,2252.62 8122.98,2252.62 8145.23,2230.37 8145.23,2185.47 8165.62,2165.09 8165.62,2060.09 v1(8166.39,2059.32)
QSFP_1_LP_MODE_3V3: J30.31 U8.10 | length 2683.9
  L1-TOP w5: v1(7031.48,470.37) 7031.48,452.65 7062.87,421.26 J30.31@7103.15,421.26 ; v1(8165.35,2007.87) 8216.54,2059.05 U8.10@8285.43,2059.05
  L3-SIG w5: v1(7031.48,470.37) 7031.48,547.23 7048.99,564.73 7261.78,564.73 7275.1,578.06 7275.1,1188.49 7377.95,1291.34 7377.95,1565.44 7520.91,1708.4 7601.64,1708.4 7668.83,1775.59 8113.07,1775.59 8166.39,1828.91 8166.39,2006.83 v1(8165.35,2007.87)
QSFP_1_MODPRS_B: MC2.126 U8.2 | length 6428.4
  L1-TOP w4.5: v1(4556.9,-1608.35) 4557,-1608.25 4557,-1558.74 MC2.126@4557.1,-1558.65 ; U8.2@8059.06,2135.83 v1(8106.3,2135.83)
  L3-SIG w4.5: v1(4556.9,-1608.35) 4556.9,-1471.94 4555.12,-1470.16 4555.12,-1469.32 4549.74,-1463.95 4549.74,-1231.59 4709.42,-1071.91 4709.42,507.98 5215.59,1014.15 5565.74,1014.15 6326.77,1775.18 6326.77,1826.77 6475.4,1975.4 7223.43,1975.4 7426,2177.96 7630.72,2177.96 7642.32,2189.57 8033.11,2189.57 8086.85,2135.83 v1(8106.3,2135.83)
QSFP_1_MODPRS_B_3V3: J30.27 R43.1 U8.13 | length 2663.3
  L1-TOP w5: v1(8202.75,2135.68) 8202.82,2135.75 8285.36,2135.75 U8.13@8285.43,2135.83 8322.83,2135.83 8346.2,2159.19 R43.1@8346.2,2186.25
  L3-SIG w5: v1(7067.69,547.24) 7266.91,547.24 7291.1,571.43 7291.1,1181.86 7393.95,1284.71 7393.95,1558.82 7527.54,1692.4 7608.27,1692.4 7675.46,1759.59 8119.7,1759.59 8202.75,1842.64 8202.75,2040.36 8202.97,2040.58 8202.97,2103.9 8202.75,2104.12 v1(8202.75,2135.68)
QSFP_1_MODSEL_B: MC2.122 U8.4 | length 6693.1
  L1-TOP w4.5: v1(4517.53,-1608.35) 4517.63,-1608.25 4517.63,-1558.74 MC2.122@4517.73,-1558.65 ; U8.4@8059.06,2084.64 8059.59,2085.18 v1(8144.64,2085.18)
  L3-SIG w4.5: v1(4517.53,-1608.35) 4517.53,-1493.91 4494.27,-1470.65 4494.27,-1246.04 4680.42,-1059.9 4680.42,519.99 5203.58,1043.15 5553.73,1043.15 6297.77,1787.19 6297.77,1838.78 6463.38,2004.4 7211.41,2004.4 7444.89,2237.87 8116.87,2237.87 8125.98,2228.76 8125.98,2176.39 8144.64,2157.73 v1(8144.64,2085.18)
QSFP_1_MODSEL_B_3V3: J30.8 U8.11 | length 2517.8
  L1-TOP w5: J30.8@7201.97,437.01 v1(7334.66,437.01) ; v1(8240.16,2084.64) U8.11@8285.43,2084.64
  L3-SIG w5: v1(7334.66,437.01) 7334.66,570.85 7323.1,582.41 7323.1,1166.71 7425.95,1269.56 7425.95,1545.56 7540.79,1660.4 7621.52,1660.4 7688.71,1727.59 8132.96,1727.59 8240.16,1834.79 v1(8240.16,2084.64)
QSFP_1_RESET_B: MC2.124 U8.3 | length 6604.9
  L1-TOP w4.5: v1(4537.09,-1648.46) 4537.25,-1648.3 4537.25,-1558.81 MC2.124@4537.42,-1558.65 ; U8.3@8059.06,2110.24 v1(8125.98,2110.24)
  L3-SIG w4.5: v1(4537.09,-1648.46) 4535.24,-1646.61 4535.24,-1225.58 4694.92,-1065.91 4694.92,513.98 5209.59,1028.65 5559.74,1028.65 6312.27,1781.19 6312.27,1832.78 6469.39,1989.9 7217.42,1989.9 7419.99,2192.46 7624.71,2192.46 7636.32,2204.07 8039.12,2204.07 8083.17,2160.02 8107.7,2160.02 8125.98,2141.73 v1(8125.98,2110.24)
QSFP_1_RESET_B_3V3: J30.9 U8.12 | length 2497.7
  L1-TOP w5: J30.9@7201.97,468.5 v1(7307.1,468.5) ; v1(8220.47,2110.24) U8.12@8285.43,2110.24
  L3-SIG w5: v1(7307.1,468.5) 7307.1,1175.23 7409.95,1278.08 7409.95,1552.19 7534.17,1676.4 7614.9,1676.4 7682.09,1743.59 8126.33,1743.59 8220.47,1837.73 v1(8220.47,2110.24)
QSFP_1_RX1N: J30.18 MC3.51 | length 2011.9
  L1-TOP w4.2: MC3.51@5594.11,147.65 5597.65,151.2 5665.08,151.2 5669.29,155.41 5814.74,300.85 6015.52,300.85 6314.68,600.01 6314.68,624.4 6300.25,638.83 6300.25,645.83 v1(6299.29,646.79)
  L8-BOT w4.2: v1(6299.29,646.79) 6301.93,644.15 6301.93,637.14 6307.46,631.61 6806.71,631.61 6982.97,807.88 7097.64,807.88 7162.99,742.52 7228.35,742.52 7233.7,747.87 v1(7237.43,747.87)
QSFP_1_RX1P: J30.17 MC3.49 | length 2011.9
  L1-TOP w4.2: MC3.49@5594.11,167.34 5597.65,163.8 5659.86,163.8 5669.29,173.23 5809.52,313.45 6010.3,313.45 6240.64,543.79 6242.13,545.28 ccw(c6238.71,548.7) 6242.13,552.12 6238.65,555.6 cw(c6242.08,559.02) 6238.66,562.44 6248.92,572.71 cw(c6252.34,569.29) 6255.77,572.71 6259.24,569.23 ccw(c6262.66,572.66) 6266.09,569.23 6283.38,586.53 6302.08,605.23 6302.08,619.18 6291.34,629.92 6284.34,629.92 v1(6283.38,630.88)
  L8-BOT w4.2: v1(6283.38,630.88) 6286.02,628.24 6293.02,628.24 6302.25,619.01 6811.93,619.01 6988.19,795.28 7092.42,795.28 7157.77,729.92 7228.35,729.92 7233.7,724.57 v1(7237.43,724.57)
QSFP_1_RX2N: J30.21 MC3.47 | length 1801.5
  L1-TOP w4.2: MC3.47@5594.11,206.71 5597.65,210.25 5645.39,210.25 5669.29,234.15 5788.68,353.54 5989.47,353.54 6066.48,430.55 6066.48,459.21 6053.9,471.79 6053.9,478.79 v1(6051.26,481.43) ; v1(6716.54,482.12) 6720.27,482.12 6725.22,477.17 6752.76,477.17 7002.36,726.77 7067.36,726.77 7069.82,729.23 7069.82,731.43 7074.61,736.22 J30.21@7103.15,736.22
  L8-BOT w4.2: v1(6051.26,481.43) 6053.9,478.79 6053.9,471.79 6059.18,466.51 6501.94,466.51 6512.6,477.17 6707.85,477.17 6712.8,482.12 v1(6716.54,482.12)
QSFP_1_RX2P: J30.22 MC3.45 | length 1801.5
  L1-TOP w4.2: MC3.45@5594.11,226.39 5597.65,222.85 5640.17,222.85 5669.29,251.97 5783.46,366.14 5984.25,366.14 5993.89,375.78 5995.38,377.27 ccw(c5991.96,380.69) 5995.38,384.11 5991.9,387.59 cw(c5995.33,391.01) 5991.9,394.43 6002.17,404.7 cw(c6005.59,401.28) 6009.02,404.7 6012.49,401.22 ccw(c6015.91,404.65) 6019.33,401.22 6037.99,419.88 6053.88,435.77 6053.88,453.99 6044.99,462.88 6037.99,462.88 v1(6035.35,465.52) ; v1(6716.54,459.62) 6720.27,459.62 6725.22,464.57 6757.98,464.57 7007.58,714.17 7067.36,714.17 7069.82,711.71 7069.82,709.51 7074.61,704.72 J30.22@7103.15,704.72
  L8-BOT w4.2: v1(6035.35,465.52) 6037.99,462.88 6044.99,462.88 6053.96,453.91 6507.16,453.91 6517.82,464.57 6707.85,464.57 6712.8,459.62 v1(6716.54,459.62)
QSFP_1_RX3N: J30.15 MC3.43 | length 1920.4
  L1-TOP w4.2: MC3.43@5594.11,265.76 5597.65,269.31 5637.52,269.31 5669.29,301.08 5769,400.79 5823.34,400.79 5922.05,499.49 5922.05,520.97 5910.48,532.53 5910.48,539.53 v1(5909.53,540.49)
  L8-BOT w4.2: v1(5909.53,540.49) 5912.17,537.85 5912.17,530.85 5923.33,519.69 5933.07,519.69 5992.18,578.79 6820.81,578.79 6954.62,712.6 7108.48,712.6 7173.05,648.03 7228.35,648.03 7233.7,653.38 v1(7237.43,653.38)
QSFP_1_RX3P: J30.14 MC3.41 | length 1920.4
  L1-TOP w4.2: MC3.41@5594.11,285.45 5597.65,281.91 5632.3,281.91 5669.29,318.9 5763.78,413.39 5818.12,413.39 5848.74,444 5850.23,445.49 ccw(c5846.8,448.91) 5850.23,452.33 5846.75,455.81 cw(c5850.18,459.23) 5846.75,462.65 5857.02,472.92 cw(c5860.44,469.5) 5863.86,472.92 5867.34,469.44 ccw(c5870.76,472.87) 5874.18,469.44 5885.44,480.7 5909.45,504.71 5909.45,515.75 5901.57,523.62 5894.57,523.62 v1(5893.62,524.58)
  L8-BOT w4.2: v1(5893.62,524.58) 5896.26,521.94 5903.26,521.94 5918.11,507.09 5938.29,507.09 5997.4,566.19 6826.03,566.19 6959.84,700 7103.26,700 7167.83,635.43 7228.35,635.43 7233.7,630.09 v1(7237.43,630.09)
QSFP_1_RX4N: J30.24 MC3.39 | length 1659
  L1-TOP w4.2: MC3.39@5594.11,521.67 5597.65,525.21 5634.17,525.21 5711.01,525.21 5749.07,487.15 5749.07,468.5 5744.12,463.55 v1(5744.12,461.3)
  L8-BOT w4.2: v1(5744.12,461.3) 5744.12,465.03 5749.07,469.98 5749.07,491.3 5770.37,512.6 5808.37,512.6 5848.53,472.44 5952.76,472.44 6012.6,532.29 6847.25,532.29 6964.57,649.61 7029.51,649.61 7046.84,632.28 7058.61,632.28 7063.95,637.63 v1(7067.69,637.63)
QSFP_1_RX4P: J30.25 MC3.37 | length 1659
  L1-TOP w4.2: MC3.37@5594.11,541.35 5597.65,537.81 5628.95,537.81 5716.23,537.81 5761.67,492.37 5761.67,468.5 5766.62,463.55 v1(5766.62,461.3)
  L8-BOT w4.2: v1(5766.62,461.3) 5766.62,465.03 5761.67,469.98 5761.67,486.08 5775.59,500 5803.15,500 5843.31,459.84 5957.97,459.84 6017.82,519.69 6852.46,519.69 6969.79,637.01 7024.29,637.01 7041.62,619.68 7058.61,619.68 7063.95,614.34 v1(7067.69,614.34)
QSFP_1_SCL: MC2.123 R49.1 U9.4 | length 6814.7
  L1-TOP w5: MC2.123@4537.42,-1315.34 4537.42,-1071.49 4582.68,-1026.23 v1(4582.68,-1025.6) ; v1(8391.5,2047.35) 8391.5,2066.93 8409.21,2084.64 U9.4@8509.84,2084.64
  L3-SIG w5: v1(4582.68,-1025.6) 4582.68,-988.19 4620.67,-950.2 4620.67,544.74 5283.84,1207.91 5578.64,1207.91 6435.93,2065.2 7186.23,2065.2 7418.65,2297.62 8342.58,2297.62 8453.74,2186.46 8459.57,2180.63 8459.57,2115.43 v1(8391.5,2047.35)
QSFP_1_SCL_3V3: J30.11 R46.1 U9.11 | length 3129.7
  L1-TOP w5: J30.11@7201.97,531.5 v1(7574.82,531.5) ; U9.11@8736.22,2084.64 8818.9,2084.64 8856.3,2047.24 v1(8858.27,2047.24)
  L3-SIG w5: v1(7574.82,531.5) 8551.18,531.5 8779.53,759.84 8779.53,1931.1 8858.27,2009.84 v1(8858.27,2047.24)
QSFP_1_SDA: MC2.121 R48.1 U9.5 | length 6784.5
  L1-TOP w5: MC2.121@4517.73,-1315.34 4517.73,-1063.29 v1(4555.42,-1025.6) ; v1(8438.74,2047.35) 8440.71,2047.35 8448.05,2054.7 8448.05,2056.13 8450.98,2059.05 U9.5@8509.84,2059.05
  L3-SIG w5: v1(4555.42,-1025.6) 4555.42,-994.23 4605.67,-943.99 4605.67,550.95 5277.63,1222.91 5572.43,1222.91 6429.71,2080.2 7180.02,2080.2 7412.44,2312.62 8348.8,2312.62 8468.74,2192.68 8474.57,2186.84 8474.57,2083.19 v1(8438.74,2047.35)
QSFP_1_SDA_3V3: J30.12 R47.1 U9.10 | length 3017.5
  L1-TOP w5: J30.12@7201.97,562.99 v1(7574.82,562.99) ; U9.10@8736.22,2059.05 8793.31,2059.05 8805.12,2047.24 v1(8807.09,2047.24)
  L3-SIG w5: v1(7574.82,562.99) 8555.12,562.99 8759.84,767.72 8759.84,2000 v1(8807.09,2047.24)
QSFP_1_TX1N: J30.37 MC3.52 | length 1788.1
  L8-BOT w4.2: v1(5321.43,146.15) 5325.17,146.15 5330.21,151.2 5550.9,151.2 5626.9,227.19 5669.29,227.19 7022.61,227.19 7037.15,241.73 7058.61,241.73 7063.95,236.39 v1(7067.69,236.39)
QSFP_1_TX1P: J30.36 MC3.50 | length 1788.1
  L8-BOT w4.2: v1(5321.43,168.84) 5325.17,168.84 5330.21,163.8 5545.69,163.8 5621.68,239.79 5669.29,239.79 7017.39,239.79 7031.93,254.33 7058.61,254.33 7063.95,259.68 v1(7067.69,259.68)
QSFP_1_TX2N: J30.2 MC3.48 | length 1967.2
  L8-BOT w4.2: v1(5380.17,205.21) 5383.91,205.21 5388.95,210.25 5513.4,210.25 5574.16,271.01 5669.29,271.01 6788.83,271.01 6879.23,361.42 7034.15,361.42 7138.09,257.48 7228.35,257.48 7233.7,252.13 v1(7237.43,252.13)
QSFP_1_TX2P: J30.3 MC3.46 | length 1967.2
  L8-BOT w4.2: v1(5380.17,227.89) 5383.91,227.89 5388.95,222.85 5508.18,222.85 5568.94,283.61 5669.29,283.61 6783.61,283.61 6874.02,374.02 7039.37,374.02 7143.31,270.08 7228.35,270.08 7233.7,275.43 v1(7237.43,275.43)
QSFP_1_TX3N: J30.34 MC3.44 | length 1840.6
  L1-TOP w4.2: v1(6716.54,327.89) 6720.27,327.89 6725.22,332.84 6805.28,332.84 6832.57,360.13 7013.54,360.13 7037.45,336.22 7067.36,336.22 7069.82,333.76 7069.82,331.56 7074.61,326.77 J30.34@7103.15,326.77
  L8-BOT w4.2: v1(5321.43,264.26) 5325.17,264.26 5330.21,269.31 5489.78,269.31 5553.32,332.84 5669.29,332.84 6707.85,332.84 6712.8,327.89 v1(6716.54,327.89)
QSFP_1_TX3P: J30.33 MC3.42 | length 1840.6
  L1-TOP w4.2: v1(6716.54,350.39) 6720.27,350.39 6725.22,345.44 6800.07,345.44 6827.36,372.73 7018.76,372.73 7042.67,348.82 7067.36,348.82 7069.82,351.28 7069.82,353.48 7074.61,358.27 J30.33@7103.15,358.27
  L8-BOT w4.2: v1(5321.43,286.95) 5325.17,286.95 5330.21,281.91 5484.56,281.91 5548.1,345.44 5669.29,345.44 6707.85,345.44 6712.8,350.39 v1(6716.54,350.39)
QSFP_1_TX4N: J30.5 MC3.40 | length 1933.3
  L8-BOT w4.2: v1(5380.17,520.17) 5383.91,520.17 5388.95,525.21 5492.4,525.21 5608.95,408.66 5669.29,408.66 7061.71,408.66 7118.4,351.97 7228.35,351.97 7233.7,346.62 v1(7237.43,346.62)
QSFP_1_TX4P: J30.6 MC3.38 | length 1933.3
  L8-BOT w4.2: v1(5380.17,542.85) 5383.91,542.85 5388.95,537.81 5497.62,537.81 5614.17,421.26 5669.29,421.26 7066.93,421.26 7123.62,364.57 7228.35,364.57 7233.7,369.91 v1(7237.43,369.91)
QSFP_2_INT_B: MC2.127 U10.3 | length 7164
  L1-TOP w5: v1(4574.8,-1059.06) 4575.8,-1060.05 4575.8,-1314.35 MC2.127@4576.79,-1315.34 ; U10.3@8952.76,2208.66 v1(8952.76,2242.13)
  L3-SIG w5: v1(4574.8,-1059.06) 4539.48,-1059.06 4518.02,-1037.59 4518.02,-995.79 4590.67,-923.14 4590.67,557.16 5271.42,1237.91 5566.21,1237.91 6423.5,2095.2 7173.8,2095.2 7406.43,2327.82 8827.38,2327.82 8842.08,2342.52 8920.23,2342.52 8952.76,2309.99 v1(8952.76,2242.13)
QSFP_2_INT_B_3V3: J31.28 R52.1 U10.4 | length 2772
  L1-TOP w5: v1(8925.2,2066.93) R52.1@8958.66,2066.93 8952.76,2072.83 U10.4@8952.76,2122.05
  L3-SIG w5: v1(7067.67,1539.37) 7127.63,1539.37 7194.04,1472.96 7257.63,1472.96 7293.59,1437.01 7344.93,1437.01 7362.2,1454.28 7362.2,1571.61 7514.49,1723.9 7595.22,1723.9 7906.75,2035.43 8175.9,2035.43 8187.47,2047 8187.47,2097.48 8180.62,2104.33 8180.62,2150.66 8191.38,2161.42 8279.53,2161.42 8326.77,2114.17 8326.77,2007.87 8356.62,1978.03 8442.6,1978.03 8655.7,2191.13 8754.12,2191.13 8775.59,2212.6 8858.27,2212.6 8925.2,2145.67 v1(8925.2,2066.93)
QSFP_2_LP_MODE: MC2.128 U11.5 | length 6309.2
  L1-TOP w4.5: v1(4576.46,-1648.46) 4576.62,-1648.3 4576.62,-1558.81 MC2.128@4576.79,-1558.65 ; U11.5@7661.42,2059.05 7661.68,2059.32 v1(7768.76,2059.32)
  L3-SIG w4.5: v1(4576.46,-1648.46) 4576.46,-1470.16 4564.24,-1457.94 4564.24,-1237.59 4723.92,-1077.92 4723.92,501.97 5221.6,999.65 5571.75,999.65 6068.16,1496.06 6696.85,1496.06 6937.01,1736.22 6937.01,1841.05 7056.86,1960.9 7229.43,1960.9 7432,2163.46 7636.73,2163.46 7648.33,2175.07 7726.4,2175.07 7768.76,2132.71 v1(7768.76,2059.32)
QSFP_2_LP_MODE_3V3: J31.31 U11.10 | length 1257.6
  L1-TOP w5: v1(7031.46,1493.99) 7031.46,1476.28 7062.86,1444.88 J31.31@7103.13,1444.88 ; v1(7768.76,2027.56) 7802.17,2027.56 7833.66,2059.05 U11.10@7887.8,2059.05
  L3-SIG w5: v1(7031.46,1493.99) 7031.46,1564.29 7055.58,1588.4 7289.19,1588.4 7488.19,1787.4 7568.92,1787.4 7768.76,1987.24 v1(7768.76,2027.56)
QSFP_2_MODPRS_B: MC2.134 U11.2 | length 5927.3
  L1-TOP w4.5: v1(4635.64,-1608.35) 4635.74,-1608.25 4635.74,-1558.74 MC2.134@4635.84,-1558.65 ; U11.2@7661.42,2135.83 7697.84,2135.83 v1(7706.92,2126.75)
  L3-SIG w4.5: v1(4635.64,-1608.35) 4635.64,-1227.71 4767.42,-1095.94 4767.42,483.95 5217.78,934.32 5527.56,934.32 5567.93,934.32 6086.18,1452.56 6714.87,1452.56 6980.51,1718.2 6980.51,1823.03 7003.26,1845.78 7219.8,1845.78 7488.19,2114.17 7694.35,2114.17 v1(7706.92,2126.75)
QSFP_2_MODPRS_B_3V3: J31.27 R53.1 U11.13 | length 1229.5
  L1-TOP w5: v1(7795.37,2135.87) U11.13@7880.84,2135.85 ; U11.13@7887.8,2135.83 7925.2,2135.83 7948.56,2159.19 R53.1@7948.56,2186.25
  L3-SIG w5: v1(7067.67,1570.87) 7294.28,1570.87 7494.82,1771.4 7575.55,1771.4 7795.37,1991.23 v1(7795.37,2135.87)
QSFP_2_MODSEL_B: MC2.130 U11.4 | length 6133.5
  L1-TOP w4.5: v1(4596.27,-1608.35) 4596.37,-1608.25 4596.37,-1558.74 MC2.130@4596.47,-1558.65 ; U11.4@7661.42,2084.64 7661.96,2085.18 v1(7747.01,2085.18)
  L3-SIG w4.5: v1(4596.27,-1608.35) 4596.27,-1466.35 4578.74,-1448.82 4578.74,-1243.6 4738.42,-1083.92 4738.42,495.96 5227.61,985.15 5577.76,985.15 6074.16,1481.56 6702.86,1481.56 6951.51,1730.21 6951.51,1835.04 7062.86,1946.4 7235.44,1946.4 7438.01,2148.96 7642.73,2148.96 7654.34,2160.57 7720.4,2160.57 7748.03,2132.93 7748.03,2086.21 v1(7747.01,2085.18)
QSFP_2_MODSEL_B_3V3: J31.8 U11.11 | length 1064.3
  L1-TOP w5: J31.8@7201.95,1460.63 v1(7334.65,1460.63) ; v1(7834.65,2084.64) U11.11@7887.8,2084.64
  L3-SIG w5: v1(7334.65,1460.63) 7334.65,1565.98 7508.07,1739.4 7588.8,1739.4 7834.65,1985.25 v1(7834.65,2084.64)
QSFP_2_RESET_B: MC2.132 U11.3 | length 6102.6
  L1-TOP w4.5: v1(4615.83,-1648.46) 4615.99,-1648.3 4615.99,-1558.81 MC2.132@4616.16,-1558.65 ; U11.3@7661.42,2110.24 v1(7728.35,2110.24)
  L3-SIG w4.5: v1(4615.83,-1648.46) 4615.83,-1227.02 4752.92,-1089.93 4752.92,489.96 5211.78,948.82 5561.93,948.82 6080.17,1467.06 6708.86,1467.06 6966.01,1724.21 6966.01,1829.03 7068.87,1931.9 7241.45,1931.9 7444.01,2134.46 7648.74,2134.46 7660.34,2146.07 7714.39,2146.07 7728.35,2132.11 v1(7728.35,2110.24)
QSFP_2_RESET_B_3V3: J31.9 U11.12 | length 1054
  L1-TOP w5: J31.9@7201.95,1492.13 v1(7307.09,1492.13) ; v1(7814.96,2110.24) 7819.28,2110.24 U11.12@7887.8,2110.24
  L3-SIG w5: v1@7307.28,1492.31 v1(7307.09,1492.13) 7307.09,1561.04 7501.44,1755.4 7582.17,1755.4 7814.96,1988.19 v1(7814.96,2110.24)
QSFP_2_RX1N: J31.18 MC3.35 | length 2308.9
  L1-TOP w4.2: MC3.35@5594.11,580.72 5597.65,584.27 5669.29,584.27 5717.54,584.27 6016.54,883.27 6016.54,1017.03 5997.1,1036.47 5997.1,1043.47 v1(5996.14,1044.42)
  L8-BOT w4.2: v1(5996.14,1044.42) 5998.78,1041.78 5998.78,1034.78 6007.28,1026.29 6022.35,1026.29 6043.86,1047.79 6043.86,1098.97 6484.25,1539.37 6732.28,1539.37 6959.06,1766.14 7228.34,1766.14 7233.68,1771.49 v1(7237.42,1771.49)
QSFP_2_RX1P: J31.17 MC3.33 | length 2308.9
  L1-TOP w4.2: MC3.33@5594.11,600.41 5597.65,596.87 5669.29,596.87 5712.32,596.87 6003.94,888.49 6003.94,921.26 6003.94,923.36 ccw(c5999.1,923.36) 5999.1,928.2 5994.18,928.2 cw(c5994.18,933.04) 5989.34,933.04 5989.34,947.56 cw(c5994.18,947.56) 5994.18,952.4 5999.1,952.4 ccw(c5999.1,957.24) 6003.94,957.24 6003.94,992.13 6003.94,1011.81 5988.19,1027.56 5981.19,1027.56 v1(5980.23,1028.51)
  L8-BOT w4.2: v1(5980.23,1028.51) 5982.87,1025.87 5989.88,1025.87 6002.06,1013.69 6027.57,1013.69 6056.46,1042.57 6056.46,1093.76 6489.47,1526.77 6737.5,1526.77 6964.27,1753.54 7228.34,1753.54 7233.68,1748.2 v1(7237.42,1748.2)
QSFP_2_RX2N: J31.21 MC3.31 | length 2165.3
  L1-TOP w4.2: MC3.31@5594.11,639.78 5597.65,643.32 5648.85,643.32 5761.44,755.91 5775.59,755.91 5785.66,745.83 5785.66,742.35 v1(5783.9,740.59) ; v1(6582.68,1678.97) 6586.41,1678.97 6591.36,1674.02 6841.24,1674.02 6917.61,1750.39 7067.34,1750.39 7069.8,1752.85 7069.8,1755.05 7074.59,1759.84 J31.21@7103.13,1759.84
  L8-BOT w4.2: v1(5783.9,740.59) 5781.26,743.23 5781.26,750.23 5747.43,784.07 5747.43,940.49 6480.96,1674.02 6575.3,1674.02 6580.25,1678.97 v1(6582.68,1678.97)
QSFP_2_RX2P: J31.22 MC3.29 | length 2165.3
  L1-TOP w4.2: MC3.29@5594.11,659.46 5597.65,655.92 5643.63,655.92 5756.22,768.51 5780.81,768.51 5794.57,754.74 5796.33,756.5 v1(5799.81,756.5) ; v1(6582.68,1656.47) 6586.41,1656.47 6591.36,1661.42 6846.46,1661.42 6852.76,1667.72 6871.35,1686.31 cw(c6874.78,1682.89) 6878.2,1686.31 6881.67,1682.84 ccw(c6885.09,1686.26) 6888.52,1682.84 6898.78,1693.11 ccw(c6895.36,1696.53) 6898.78,1699.95 6895.31,1703.43 cw(c6898.73,1706.85) 6895.31,1710.27 6909.45,1724.41 6922.83,1737.79 7067.34,1737.79 7069.8,1735.33 7069.8,1733.14 7074.59,1728.35 J31.22@7103.13,1728.35
  L8-BOT w4.2: v1(5799.81,756.5) 5797.17,759.14 5790.17,759.14 5760.03,789.29 5760.03,935.27 6486.18,1661.42 6575.3,1661.42 6580.25,1656.47 v1(6582.68,1656.47)
QSFP_2_RX3N: J31.15 MC3.27 | length 2152.9
  L1-TOP w4.2: MC3.27@5594.11,698.83 5597.65,702.38 5645.39,702.38 5669.29,726.28 5748.25,805.23 5822.16,805.23 5843.31,826.38 5843.31,851.03 5825.95,868.39 5825.95,875.39 v1(5823.31,878.03)
  L8-BOT w4.2: v1(5823.31,878.03) 5825.95,875.39 5825.95,868.39 5836.12,858.22 5917.28,858.22 6090.55,1031.5 6090.55,1074.8 6504.97,1489.22 6756.94,1489.22 6939.37,1671.65 7228.34,1671.65 7233.68,1677 v1(7237.42,1677)
QSFP_2_RX3P: J31.14 MC3.25 | length 2152.9
  L1-TOP w4.2: MC3.25@5594.11,718.52 5597.65,714.98 5640.17,714.98 5669.29,744.09 5743.03,817.83 5816.94,817.83 5830.71,831.6 5830.71,845.82 5817.04,859.48 5810.04,859.48 v1(5807.4,862.12)
  L8-BOT w4.2: v1(5807.4,862.12) 5810.04,859.48 5817.04,859.48 5830.9,845.62 5922.5,845.62 6103.15,1026.28 6103.15,1069.58 6510.19,1476.62 6762.16,1476.62 6768.46,1482.92 6787.06,1501.52 cw(c6790.48,1498.1) 6793.9,1501.52 6797.38,1498.05 ccw(c6800.8,1501.47) 6804.22,1498.05 6814.49,1508.32 ccw(c6811.07,1511.74) 6814.49,1515.16 6811.01,1518.63 cw(c6814.44,1522.06) 6811.01,1525.48 6841.59,1556.05 6944.59,1659.05 7228.34,1659.05 7233.68,1653.71 v1(7237.42,1653.71)
QSFP_2_RX4N: J31.24 MC3.23 | length 1987.4
  L1-TOP w4.2: MC3.23@5594.11,757.89 5597.65,761.43 5634.17,761.43 5833.37,960.63 5885.83,960.63 5893.7,952.76 5893.7,945.76 v1(5894.66,944.8) ; v1(6700.79,1612.28) 6704.52,1612.28 6709.47,1607.33 6864.83,1607.33 6939.39,1681.89 7021.83,1681.89 7047.82,1655.91 7067.34,1655.91 7069.8,1658.37 7069.8,1660.56 7074.59,1665.35 J31.24@7103.13,1665.35
  L8-BOT w4.2: v1(5894.66,944.8) 5892.02,947.44 5892.02,954.44 5877.95,968.5 5877.95,1004.14 6481.15,1607.33 6692.1,1607.33 6697.05,1612.28 v1(6700.79,1612.28)
QSFP_2_RX4P: J31.25 MC3.21 | length 1987.4
  L1-TOP w4.2: MC3.21@5594.11,777.57 5597.65,774.03 5628.95,774.03 5828.15,973.23 5891.05,973.23 5902.61,961.67 5909.61,961.67 v1(5910.57,960.71) ; v1(6700.79,1589.78) 6704.52,1589.78 6709.47,1594.73 6870.05,1594.73 6888.65,1613.33 cw(c6892.07,1609.91) 6895.49,1613.33 6898.96,1609.86 ccw(c6902.39,1613.28) 6905.81,1609.86 6916.08,1620.13 ccw(c6912.65,1623.55) 6916.08,1626.97 6912.6,1630.44 cw(c6916.03,1633.87) 6912.6,1637.29 6925.65,1650.34 6944.61,1669.29 7016.61,1669.29 7042.6,1643.31 7067.34,1643.31 7069.8,1640.85 7069.8,1638.65 7074.59,1633.86 J31.25@7103.13,1633.86
  L8-BOT w4.2: v1(5910.57,960.71) 5907.93,963.35 5900.92,963.35 5890.55,973.72 5890.55,998.92 6486.36,1594.73 6692.1,1594.73 6697.05,1589.78 v1(6700.79,1589.78)
QSFP_2_SCL: MC2.131 R50.1 U9.2 | length 6537.1
  L1-TOP w5: MC2.131@4616.29,-1315.21 4617.13,-1314.36 4617.13,-1020.66 v1(4618.11,-1019.68) ; v1(8438.74,2149.72) 8458.55,2149.72 8472.44,2135.83 U9.2@8509.84,2135.83
  L3-SIG w5: v1(4618.11,-1019.68) 4635.67,-1002.13 4635.67,538.53 5290.06,1192.91 5584.85,1192.91 6442.14,2050.2 7192.44,2050.2 7424.87,2282.62 8336.37,2282.62 8438.74,2180.25 v1(8438.74,2149.72)
QSFP_2_SCL_3V3: J31.11 R44.1 U9.13 | length 1928
  L1-TOP w5: J31.11@7201.95,1555.12 v1(7574.8,1555.12) ; U9.13@8736.22,2135.83 8768.62,2135.83 8782.4,2149.61 v1(8807.09,2149.61)
  L3-SIG w5: v1(7574.8,1555.12) 8181.13,1555.12 8775.62,2149.61 v1(8807.09,2149.61)
QSFP_2_SDA: MC2.133 R51.1 U9.3 | length 6560.3
  L1-TOP w5: MC2.133@4635.84,-1315.34 4636.82,-1314.36 4636.82,-1040.35 v1(4637.8,-1039.37) ; v1(8391.5,2149.72) 8393.46,2149.72 8413.15,2130.03 8456.46,2130.03 8476.25,2110.24 U9.3@8509.84,2110.24
  L3-SIG w5: v1(4637.8,-1039.37) 4650.67,-1026.5 4650.67,532.31 5191.26,1072.9 5541.41,1072.9 6268.02,1799.52 6268.02,1851.11 6451.06,2034.15 7199.09,2034.15 7432.57,2267.62 8330.16,2267.62 8391.5,2206.28 v1(8391.5,2149.72)
QSFP_2_SDA_3V3: J31.12 R45.1 U9.12 | length 2044.4
  L1-TOP w5: J31.12@7201.95,1586.61 v1(7574.8,1586.61) ; U9.12@8736.22,2110.24 8766.52,2110.24 8786.2,2129.92 8836.61,2129.92 v1(8856.3,2149.61) R45.1@8858.27,2149.61
  L3-SIG w5: v1(7574.8,1586.61) 8181.13,1586.61 8766.45,2171.93 8833.97,2171.93 v1(8856.3,2149.61)
QSFP_2_TX1N: J31.37 MC3.36 | length 2077.7
  L8-BOT w4.2: v1(5321.43,579.22) 5325.17,579.22 5330.21,584.27 5592.7,584.27 5622.54,554.42 5669.29,554.42 5869.01,554.42 6289.49,974.9 6289.49,1009.64 6523.94,1244.09 7025.56,1244.09 7046.82,1265.35 7058.59,1265.35 7063.94,1260.01 v1(7067.67,1260.01)
QSFP_2_TX1P: J31.36 MC3.34 | length 2077.7
  L8-BOT w4.2: v1(5321.43,601.91) 5325.17,601.91 5330.21,596.87 5597.91,596.87 5627.76,567.02 5669.29,567.02 5863.79,567.02 6276.89,980.12 6276.89,1014.86 6518.73,1256.69 7020.34,1256.69 7041.6,1277.95 7058.59,1277.95 7063.94,1283.3 v1(7067.67,1283.3)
